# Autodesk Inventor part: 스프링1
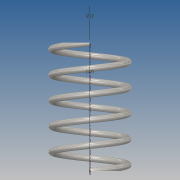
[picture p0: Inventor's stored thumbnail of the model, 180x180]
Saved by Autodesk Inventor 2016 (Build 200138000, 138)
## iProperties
Created: 2016-01
Part Number: 스프링1
Material: 스테인레스 스틸
Document SubType Name: Modeling
Designer: Administrator
Density: 8 g/cm^3
Appearance: 반연마
Mass: 8.59076 g
Surface Area: 21.7382 cm^2
Volume: 1.07385 cm^3
Author: Administrator
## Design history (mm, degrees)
sketch "스케치1"
  geometry: L1 (0, 0)-(11, 0); L2 (11, 0)-(11, 25.358); L3 (11, 25.358)-(0, 25.358); L4 (0, 25.358)-(0, 0); C1 r 1 at (11, 0)
  constraints: 8 end point, 2 parallel, 1 centre point, 1 coincident, 1 horizontal, 1 perpendicular
  dimensions: "d0" = 2 diameter of C1; "d1" = 25.35829 distance of L1.end L2.end (derived); "d2" = 22 diameter of L2 L4
feature "코일1" pitch "d3" = 10; turns "d5" = 5; dims "d4" = 25.35829 (= d1), "d6" = 0, angle "d7" = 90 deg, angle "d8" = 90 deg, "d9" = 0, "d10" = 0
sketch "스케치2"
  geometry: L1 (5.3, 0)-(-21.597, 0); L2 (-21.597, 0)-(-21.597, -10.619); L3 (-21.597, -10.619)-(5.3, -10.619); L4 (5.3, -10.619)-(5.3, 0); 3 further points
  constraints: 8 end point, 2 parallel, 1 horizontal, 1 horizontal alignment, 1 perpendicular, 1 point on line
extrude "돌출1" cut sketch "스케치2" stored distance "d11" = 0; taper "d12" = 0 deg
sketch "스케치3"
  geometry: L1 (-4.261, 0)-(22.454, 0); L2 (22.454, 0)-(22.454, 6.999); L3 (22.454, 6.999)-(-4.261, 6.999); L4 (-4.261, 6.999)-(-4.261, 0); 3 further points
  constraints: 8 end point, 2 parallel, 1 horizontal, 1 horizontal alignment, 1 perpendicular, 1 point on line
extrude "돌출2" cut sketch "스케치3" stored distance "d13" = 0; taper "d14" = 0 deg
node "솔리드1"
